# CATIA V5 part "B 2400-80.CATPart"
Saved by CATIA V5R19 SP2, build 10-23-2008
Part number: B 2400-80
Bounding box of the stored display mesh (mm): x -37.351 to 37.351, y -37.351 to 37.351, z 0 to 270
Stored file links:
  C:\Users\Bora\Desktop\3D Katı model\B serisi\B 2400\B 2400-80.CATPart
  C:\Program Files\Dassault Systemes\B19\intel_a\reffiles\standard\MetricThickPitch.txt
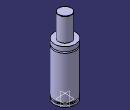
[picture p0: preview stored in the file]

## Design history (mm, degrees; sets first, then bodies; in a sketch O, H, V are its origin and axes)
Body1 (main body)
  Sketch1 on yz-plane, origin (0, 0, 0), H (0, 1, 0), V (0, 0, 1)
    point P3 (22.5, 269)
    point P5 (22.5, 269)
    point P10 (37.5, 166.5)
    point P11 (37.5, 171.5)
    point P13 (37.5, 171.5)
    point P14 (37.5, 166.5)
    line L1 (37.5, 0) -> (37.5, 8)
    line L2 (22.5, 269) -> (22.5, 187)
    arc A1 centre (21.5, 269) radius 1 from (22.5, 269) to (21.5, 270) ccw
    line L3 (33.5, 13) -> (33.5, 8)
    line L4 (37.5, 13) -> (37.5, 166.5)
    line L5 (37.5, 171.5) -> (37.5, 187)
    arc A2 centre (37.5, 169) radius 2.5 from (37.5, 171.5) to (37.5, 166.5) ccw
    line L6 (21.5, 270) -> (0, 270)
    point P15 (0, 270)
    line L7 (22.5, 187) -> (37.5, 187)
    line L8 (0, 0) -> (37.5, 0)
    line L9 (33.5, 13) -> (37.5, 13)
    line L10 (33.5, 8) -> (37.5, 8)
    coincidence: P15 V, P3 P5, P10 P14, P11 P13
    tangency: L6 A1
    horizontal: L7 H, L8 H, L9 H, L10 H
  Shaft1: profile Sketch1, axis Sketch1.V, angle 360
  Sketch2 on face of Shaft1 from Sketch1.L8, origin (0, 0, 0), H (1, 0, 0), V (0, -1, 0)
    point P1 (20, 0)
    distance P1 V = 20
  Hole1: placed by Sketch2, at (20, 0, 0) direction (0, 0, 1), diameter 6.647, depth 13, threaded "M8", thread diameter 8, thread depth 13, pitch 1.25
  CircPattern1: of Hole1, instances 4, angular step 90, axis from xy-plane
